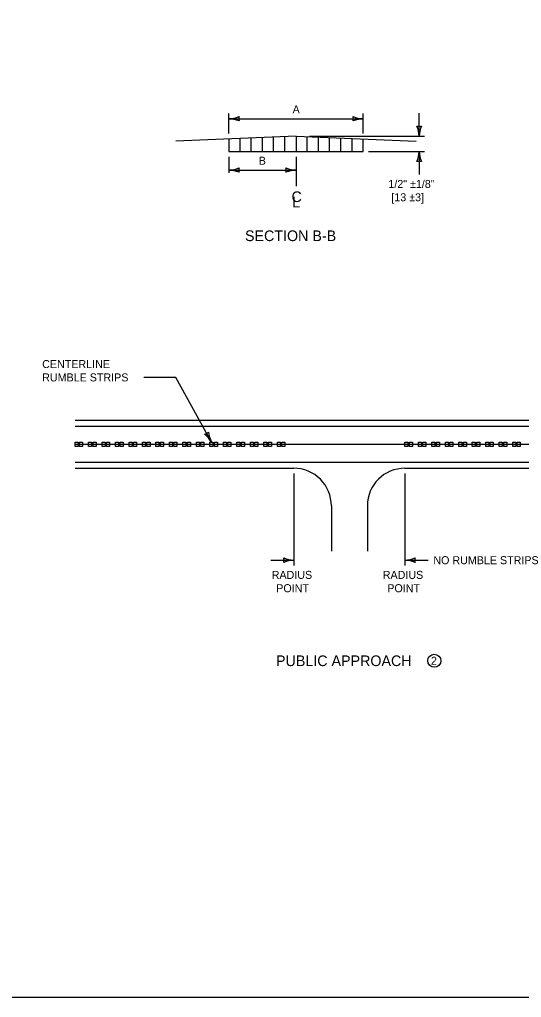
# Model space of a CAD drawing. Extents: x 49937 to 50080, y 49883 to 50108.
# Drawn here: x 50005.48 to 50009.24, y 49987.8 to 49995.13 of the extents above; entities that cross this region are included whole.
import ezdxf

# ---------------------------------------------------------------- set-up
doc = ezdxf.new("R2010")
doc.units = 0
for name, color, linetype in [('Level 1', 7, 'Continuous'), ('Level 2', 7, 'Continuous'), ('Level 3', 7, 'Continuous'), ('Level 5', 7, 'Continuous')]:
    doc.layers.add(name, color=color, linetype=linetype)

msp = doc.modelspace()

# ---------------------------------------------------------------- linework, layer by layer
at = {"layer": 'Level 1'}
for p, q in [((50007.55, 49994.2555), (50006.65, 49994.2195)), ((50007.4661, 49994.1411), (50007.4661, 49994.2522)), ((50007.55, 49994.2555), (50008.4499, 49994.2195)), ((50007.6339, 49994.1411), (50007.6339, 49994.2522)), ((50007.1305, 49994.1411), (50007.1305, 49994.2387)), ((50007.2144, 49994.1411), (50007.2144, 49994.2421)), ((50007.2983, 49994.1411), (50007.2983, 49994.2454)), ((50007.3822, 49994.1411), (50007.3822, 49994.2488)), ((50007.7178, 49994.1411), (50007.7178, 49994.2488)), ((50007.8017, 49994.1411), (50007.8017, 49994.2454)), ((50007.8856, 49994.1411), (50007.8856, 49994.2421)), ((50007.9695, 49994.1411), (50007.9695, 49994.2387)), ((50005.8942, 49992.1261), (50012.2641, 49992.1261)), ((50005.8942, 49992.0811), (50012.2641, 49992.0811)), ((50005.8944, 49991.8111), (50012.2641, 49991.8111)), ((50005.8944, 49991.7661), (50007.5336, 49991.7661)), ((50008.3661, 49991.7661), (50012.2641, 49991.7661)), ((50007.8148, 49991.4848), (50007.8148, 49991.1453)), ((50008.0848, 49991.4848), (50008.0848, 49991.1453))]:
    msp.add_line(p, q, dxfattribs=at)
for points in [[(49999.3835, 49998.9992), (50016.7501, 49998.9992), (50016.7501, 49987.7988), (49999.3835, 49987.7988)], [(50005.8942, 49991.9629), (50005.9167, 49991.9629), (50005.9167, 49991.9292), (50005.8942, 49991.9292)], [(50005.9271, 49991.9629), (50005.9496, 49991.9629), (50005.9496, 49991.9292), (50005.9271, 49991.9292)], [(50005.9945, 49991.9629), (50006.017, 49991.9629), (50006.017, 49991.9292), (50005.9945, 49991.9292)], [(50006.0282, 49991.9629), (50006.0507, 49991.9629), (50006.0507, 49991.9292), (50006.0282, 49991.9292)], [(50006.0956, 49991.9629), (50006.1181, 49991.9629), (50006.1181, 49991.9292), (50006.0956, 49991.9292)], [(50006.1293, 49991.9629), (50006.1518, 49991.9629), (50006.1518, 49991.9292), (50006.1293, 49991.9292)], [(50006.1967, 49991.9629), (50006.2192, 49991.9629), (50006.2192, 49991.9292), (50006.1967, 49991.9292)], [(50006.2304, 49991.9629), (50006.2529, 49991.9629), (50006.2529, 49991.9292), (50006.2304, 49991.9292)], [(50006.2978, 49991.9629), (50006.3203, 49991.9629), (50006.3203, 49991.9292), (50006.2978, 49991.9292)], [(50006.3315, 49991.9629), (50006.354, 49991.9629), (50006.354, 49991.9292), (50006.3315, 49991.9292)], [(50006.3989, 49991.9629), (50006.4214, 49991.9629), (50006.4214, 49991.9292), (50006.3989, 49991.9292)], [(50006.4326, 49991.9629), (50006.4551, 49991.9629), (50006.4551, 49991.9292), (50006.4326, 49991.9292)], [(50006.5, 49991.9629), (50006.5225, 49991.9629), (50006.5225, 49991.9292), (50006.5, 49991.9292)], [(50006.5337, 49991.9629), (50006.5562, 49991.9629), (50006.5562, 49991.9292), (50006.5337, 49991.9292)], [(50006.6011, 49991.9629), (50006.6236, 49991.9629), (50006.6236, 49991.9292), (50006.6011, 49991.9292)], [(50006.6348, 49991.9629), (50006.6573, 49991.9629), (50006.6573, 49991.9292), (50006.6348, 49991.9292)], [(50006.7022, 49991.9629), (50006.7247, 49991.9629), (50006.7247, 49991.9292), (50006.7022, 49991.9292)], [(50006.7359, 49991.9629), (50006.7584, 49991.9629), (50006.7584, 49991.9292), (50006.7359, 49991.9292)], [(50006.8033, 49991.9629), (50006.8258, 49991.9629), (50006.8258, 49991.9292), (50006.8033, 49991.9292)], [(50006.837, 49991.9629), (50006.8595, 49991.9629), (50006.8595, 49991.9292), (50006.837, 49991.9292)], [(50006.9044, 49991.9629), (50006.9269, 49991.9629), (50006.9269, 49991.9292), (50006.9044, 49991.9292)], [(50006.9381, 49991.9629), (50006.9606, 49991.9629), (50006.9606, 49991.9292), (50006.9381, 49991.9292)], [(50007.0055, 49991.9629), (50007.028, 49991.9629), (50007.028, 49991.9292), (50007.0055, 49991.9292)], [(50007.0392, 49991.9629), (50007.0617, 49991.9629), (50007.0617, 49991.9292), (50007.0392, 49991.9292)], [(50007.1066, 49991.9629), (50007.1291, 49991.9629), (50007.1291, 49991.9292), (50007.1066, 49991.9292)], [(50007.1403, 49991.9629), (50007.1628, 49991.9629), (50007.1628, 49991.9292), (50007.1403, 49991.9292)], [(50007.2077, 49991.9629), (50007.2302, 49991.9629), (50007.2302, 49991.9292), (50007.2077, 49991.9292)], [(50007.2414, 49991.9629), (50007.2639, 49991.9629), (50007.2639, 49991.9292), (50007.2414, 49991.9292)], [(50007.3088, 49991.9629), (50007.3313, 49991.9629), (50007.3313, 49991.9292), (50007.3088, 49991.9292)], [(50007.3425, 49991.9629), (50007.365, 49991.9629), (50007.365, 49991.9292), (50007.3425, 49991.9292)], [(50007.4099, 49991.9629), (50007.4324, 49991.9629), (50007.4324, 49991.9292), (50007.4099, 49991.9292)], [(50007.4436, 49991.9629), (50007.4661, 49991.9629), (50007.4661, 49991.9292), (50007.4436, 49991.9292)], [(50008.3661, 49991.9629), (50008.3886, 49991.9629), (50008.3886, 49991.9292), (50008.3661, 49991.9292)], [(50008.3998, 49991.9629), (50008.4223, 49991.9629), (50008.4223, 49991.9292), (50008.3998, 49991.9292)], [(50008.4672, 49991.9629), (50008.4897, 49991.9629), (50008.4897, 49991.9292), (50008.4672, 49991.9292)], [(50008.5009, 49991.9629), (50008.5234, 49991.9629), (50008.5234, 49991.9292), (50008.5009, 49991.9292)], [(50008.5683, 49991.9629), (50008.5908, 49991.9629), (50008.5908, 49991.9292), (50008.5683, 49991.9292)], [(50008.602, 49991.9629), (50008.6245, 49991.9629), (50008.6245, 49991.9292), (50008.602, 49991.9292)], [(50008.6694, 49991.9629), (50008.6919, 49991.9629), (50008.6919, 49991.9292), (50008.6694, 49991.9292)], [(50008.7031, 49991.9629), (50008.7256, 49991.9629), (50008.7256, 49991.9292), (50008.7031, 49991.9292)], [(50008.7705, 49991.9629), (50008.793, 49991.9629), (50008.793, 49991.9292), (50008.7705, 49991.9292)], [(50008.8042, 49991.9629), (50008.8267, 49991.9629), (50008.8267, 49991.9292), (50008.8042, 49991.9292)], [(50008.8716, 49991.9629), (50008.8941, 49991.9629), (50008.8941, 49991.9292), (50008.8716, 49991.9292)], [(50008.9053, 49991.9629), (50008.9278, 49991.9629), (50008.9278, 49991.9292), (50008.9053, 49991.9292)], [(50008.9727, 49991.9629), (50008.9952, 49991.9629), (50008.9952, 49991.9292), (50008.9727, 49991.9292)], [(50009.0064, 49991.9629), (50009.0289, 49991.9629), (50009.0289, 49991.9292), (50009.0064, 49991.9292)], [(50009.0738, 49991.9629), (50009.0963, 49991.9629), (50009.0963, 49991.9292), (50009.0738, 49991.9292)], [(50009.1075, 49991.9629), (50009.13, 49991.9629), (50009.13, 49991.9292), (50009.1075, 49991.9292)], [(50009.1749, 49991.9629), (50009.1974, 49991.9629), (50009.1974, 49991.9292), (50009.1749, 49991.9292)], [(50009.2086, 49991.9629), (50009.2311, 49991.9629), (50009.2311, 49991.9292), (50009.2086, 49991.9292)]]:
    msp.add_lwpolyline(points, close=True, dxfattribs=at)
msp.add_lwpolyline([(50007.0466, 49994.2354), (50007.0466, 49994.1411), (50008.0534, 49994.1411), (50008.0534, 49994.2354)], dxfattribs=at)
for centre, start, end in [((50007.5335, 49991.4848), 359.98981, 89.98981), ((50008.3661, 49991.4848), 90, 180)]:
    msp.add_arc(centre, 0.2813, start, end, dxfattribs=at)
at = {"layer": 'Level 2'}
msp.add_circle((50008.5865, 49990.3229), 0.0491, dxfattribs=at)
at = {"layer": 'Level 3'}
for p, q in [((50007.0466, 49994.2754), (50007.0466, 49994.4266)), ((50008.0534, 49994.2754), (50008.0534, 49994.4266)), ((50008.4734, 49994.2555), (50008.4734, 49994.4289)), ((50007.0466, 49994.3866), (50008.0534, 49994.3866)), ((50007.65, 49994.2555), (50008.5134, 49994.2555)), ((50008.0934, 49994.1411), (50008.5134, 49994.1411)), ((50008.4734, 49994.1411), (50008.4734, 49993.9677)), ((50007.0466, 49994.1011), (50007.0466, 49993.9817)), ((50007.55, 49994.1011), (50007.55, 49993.8817)), ((50007.0466, 49994.0017), (50007.55, 49994.0017)), ((50007.5335, 49991.7261), (50007.5335, 49991.0368)), ((50008.3661, 49991.7261), (50008.3661, 49991.0368)), ((50007.3601, 49991.0768), (50007.5335, 49991.0768)), ((50008.3661, 49991.0768), (50008.5395, 49991.0768))]:
    msp.add_line(p, q, dxfattribs=at)
msp.add_lwpolyline([(50006.9156, 49991.9629), (50006.6499, 49992.4472), (50006.4083, 49992.4472)], dxfattribs=at)
for centre, radius, start, end in [((50007.0351, 49994.6194), 0.233, 272.82731, 292.07716), ((50007.1748, 49994.3866), 0.0548, 162.13882, 197.86118), ((50008.0625, 49994.6088), 0.2223, 247.47031, 267.65382), ((50007.9251, 49994.3866), 0.0548, 342.15312, 17.87548), ((50007.0374, 49994.1645), 0.2223, 67.45601, 87.63952), ((50008.0649, 49994.1539), 0.233, 92.84161, 112.09146), ((50008.4734, 49994.3837), 0.0548, 252.13882, 287.86118), ((50008.2407, 49994.244), 0.233, 2.82731, 22.07716), ((50008.6955, 49994.2464), 0.2223, 157.45601, 177.63952), ((50008.2513, 49994.1502), 0.2223, 337.45601, 357.63952), ((50008.7061, 49994.1526), 0.233, 182.82731, 202.07716), ((50008.4734, 49994.0129), 0.0548, 72.13882, 107.86118), ((50007.035, 49994.2344), 0.233, 272.84161, 292.09146), ((50007.0375, 49993.7796), 0.2223, 67.47031, 87.65382), ((50007.1748, 49994.0018), 0.0548, 162.15312, 197.87548), ((50007.5591, 49994.2239), 0.2223, 247.47031, 267.65382), ((50007.4217, 49994.0017), 0.0548, 342.15312, 17.87548), ((50007.5615, 49993.769), 0.233, 92.84161, 112.09146), ((50006.8539, 49992.0753), 0.0548, 280.90656, 316.62892), ((50006.7172, 49991.8408), 0.233, 31.59505, 50.8449), ((50007.1147, 49992.0618), 0.2223, 186.22375, 206.40726), ((50007.5426, 49991.2989), 0.2223, 247.45601, 267.63952), ((50007.4053, 49991.0768), 0.0548, 342.13882, 17.86118), ((50007.545, 49990.8441), 0.233, 92.82731, 112.07716), ((50008.3546, 49991.3095), 0.233, 272.82731, 292.07716), ((50008.3569, 49990.8546), 0.2223, 67.45601, 87.63952), ((50008.4943, 49991.0768), 0.0548, 162.13882, 197.86118)]:
    msp.add_arc(centre, radius, start, end, dxfattribs=at)
at = {"layer": 'Level 5'}
for p, q in [((50007.55, 49994.2555), (50007.55, 49994.1411)), ((50005.8942, 49991.9461), (50012.2641, 49991.9461))]:
    msp.add_line(p, q, dxfattribs=at)

# ---------------------------------------------------------------- texts
at = {"layer": 'Level 2'}
for s, height, p in [('A', 0.06, (50007.5242, 49994.4266)), ('B', 0.06, (50007.2705, 49994.0417)), ('1/2" ±1/8"', 0.06, (50008.2422, 49993.8677)), (' [13 ±3]', 0.06, (50008.2422, 49993.7677)), ('SECTION B-B', 0.08, (50007.1674, 49993.4691)), ('NO RUMBLE STRIPS', 0.06, (50008.5795, 49991.0468)), ('RADIUS', 0.06, (50007.3676, 49990.9368)), ('RADIUS', 0.06, (50008.2002, 49990.9368)), ('POINT', 0.06, (50007.4016, 49990.8368)), ('POINT', 0.06, (50008.2342, 49990.8368)), ('PUBLIC APPROACH', 0.08, (50007.3999, 49990.2829)), ('2', 0.06, (50008.5613, 49990.2929))]:
    msp.add_text(s, height=height, dxfattribs=at).set_placement(p)
for s, height, p in [('C', 0.08, (50007.5159, 49993.7617)), ('L', 0.08, (50007.5217, 49993.7217)), ('CENTERLINE', 0.06, (50005.6468, 49992.5172)), ('RUMBLE STRIPS', 0.06, (50005.6468, 49992.4172))]:
    msp.add_text(s, height=height, rotation=360, dxfattribs=at).set_placement(p)

doc.saveas('drawing.dxf')
